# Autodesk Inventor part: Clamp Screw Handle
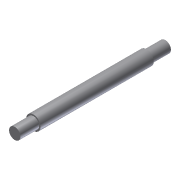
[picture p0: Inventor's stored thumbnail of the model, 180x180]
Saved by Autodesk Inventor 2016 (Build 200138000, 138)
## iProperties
Shininess: 77.0
Length Units: 11269
Angle Units: 11279
Time Units: 11290
Mass Units: 11283
Length Display Precision: 3
Angle Display Precision: 2
Compacted: True
Created: 2002-02
Part Number: Clamp Screw Handle
Document SubType Name: Modeling
Designer: ***
Density: 1 g/cm^3
Material: Generic
Appearance: Default
Density: 0.0
Volumn: 0.0
Area: 0.0
PropertySet Name: Model Information
Control State: 0
Master: False
Checked Out: False
Author: ***
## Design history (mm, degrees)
sketch "Sketch1"
  geometry: L1 (0, 105)-(4, 105); L2 (4, 105)-(4, 92); L3 (4, 92)-(5, 92); L4 (5, 92)-(5, 13); L5 (5, 13)-(4, 13); L6 (4, 13)-(4, 0); L7 (4, 0)-(0, 0); L8 (0, 0)-(0, 105)
  constraints: 16 end point, 5 parallel, 2 equal length, 1 collinear, 1 horizontal, 1 perpendicular
  dimensions: "d0" = 10 diameter of L4 L8; "d1" = 8 diameter of L2 L8; "d2" = 13 distance of L1.end L2.end; "d3" = 79 distance of L3.end L4.end
revolve "Revolution1" sketch "Sketch1" stored, may be unused: angle "d4" = 90 deg
body "Solid1"
